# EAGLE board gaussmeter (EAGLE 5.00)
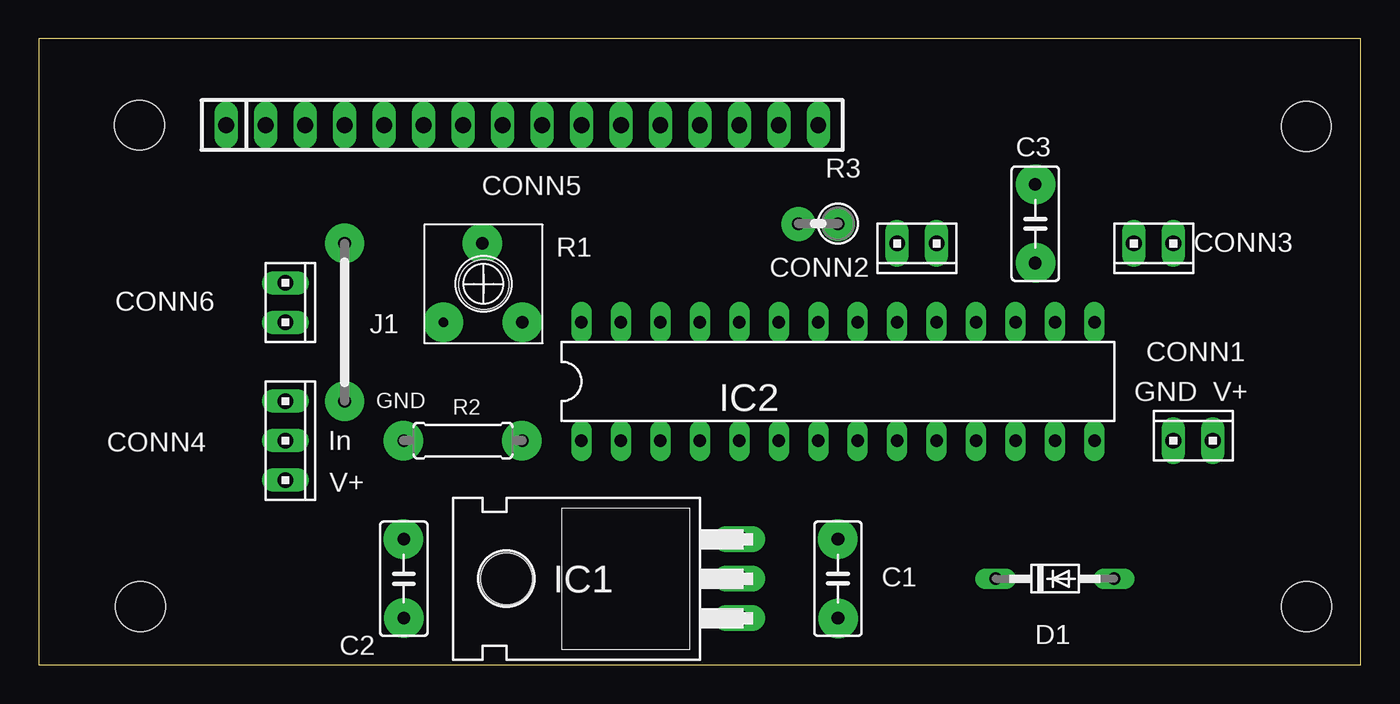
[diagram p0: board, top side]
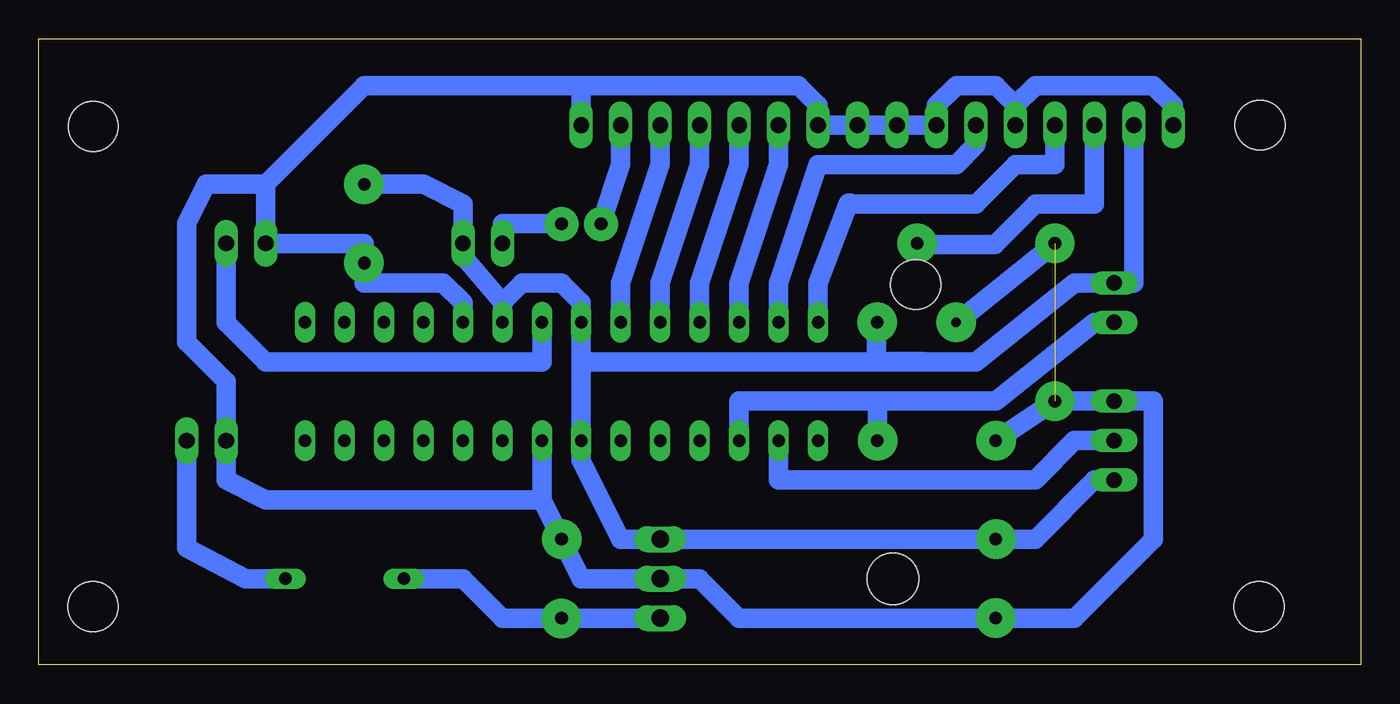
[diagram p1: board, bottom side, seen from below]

Size 85.07 x 40.31 mm. Coordinates in mm from the lower left corner, seen from the top.
Outline: 0,0 85.07,0 85.07,40.31 0,40.31 0,0
Copper layers (1*16): Top 0.035mm / dielectric 1.5mm / Bottom 0.035mm
Design rules "default *": minimum track width 50mil, minimum drill 24mil, track to track 8mil, track to pad 8mil, pad to pad 8mil, via to via 8mil, smd to smd 8mil, copper to edge 40mil, drill to drill 8mil, minimum pad ring 10mil, minimum via ring 8mil, stop-mask expansion 4mil, vias tented up to drill 0mil, thermal gap 10mil
Holes 3.2 mm at 28.63,24.49 6.48,34.75 81.57,34.67 81.59,3.76 6.54,3.76

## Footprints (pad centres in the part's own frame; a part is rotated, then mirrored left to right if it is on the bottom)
C5B3 = drill 0.813 pad 1.6 octagon: 1 -2.54,0; 2 2.54,0
10X02MTA = drill 1.016 long: 1 1.27,0; 2 -1.27,0
10X03MTA = drill 1.016 long: 1 2.54,0; 2 0,0; 3 -2.54,0
SIP-100-16V = drill 1.016 long: 1 -19.05,0; 2 -16.51,0; 3 -13.97,0; 4 -11.43,0; 5 -8.89,0; 6 -6.35,0; 7 -3.81,0; 8 -1.27,0; 9 1.27,0; 10 3.81,0; 11 6.35,0; 12 8.89,0; 13 11.43,0; 14 13.97,0; 15 16.51,0; 16 19.05,0
DO34-7 = drill 0.813 long: A 3.81,0; C -3.81,0
TO220H = drill 1.118 long: 1 -2.54,-10.16; 2 0,-10.16; 3 2.54,-10.16 | hole 3.302: 0,4.826
DIL28-3 = drill 0.813 long: 1 -16.51,-3.81; 2 -13.97,-3.81; 3 -11.43,-3.81; 4 -8.89,-3.81; 5 -6.35,-3.81; 6 -3.81,-3.81; 7 -1.27,-3.81; 8 1.27,-3.81; 9 3.81,-3.81; 10 6.35,-3.81; 11 8.89,-3.81; 12 11.43,-3.81; 13 13.97,-3.81; 14 16.51,-3.81; 15 16.51,3.81; 16 13.97,3.81; 17 11.43,3.81; 18 8.89,3.81; 19 6.35,3.81; 20 3.81,3.81; 21 1.27,3.81; 22 -1.27,3.81; 23 -3.81,3.81; 24 -6.35,3.81; 25 -8.89,3.81; 26 -11.43,3.81; 27 -13.97,3.81; 28 -16.51,3.81
10 = drill 0.813 pad 1.6 octagon: 1 -5.08,0; 2 5.08,0
TRIMMERORIZZ = drill 0.5 pad 1.016 round: P$1 -2.54,-2.54; P$2 2.54,-2.54; P$3 0,2.54
0207/7 = drill 0.813 octagon: 1 -3.81,0; 2 3.81,0
0207/2V = drill 0.813 octagon: 1 -1.27,0; 2 1.27,0

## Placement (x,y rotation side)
C1  330nF  [C5B3]  51.43,5.55 90 top
C2  100nF  [C5B3]  23.49,5.55 270 top
C3  100nF  [C5B3]  64.13,28.41 270 top
CONN1  +  [10X02MTA]  74.29,14.44 0 top
CONN2  [10X02MTA]  56.51,27.14 180 top
CONN3  [10X02MTA]  71.75,27.14 180 top
CONN4  [10X03MTA]  15.87,14.44 270 top
CONN5  [SIP-100-16V]  31.11,34.76 0 top
CONN6  [10X02MTA]  15.87,23.33 270 top
D1  1n4001  [DO34-7]  65.4,5.55 0 top
IC1  7805T  [TO220H]  34.92,5.55 90 top
IC2  PIC16F883  [DIL28-3]  51.43,18.25 0 top
J1  J10MM  [10]  19.68,22.06 90 top
R1  10k  [TRIMMERORIZZ]  28.62,24.54 0 top
R2  5k6  [0207/7]  27.3,14.44 0 top
R3  22  [0207/2V]  50.16,28.41 180 top

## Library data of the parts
C1-C3 = capacitor-wima
CONN1-CONN4 CONN6 = con-amp
CONN5 = con-hdrs40
D1 = diode
IC1 = linear
IC2 = microchip
J1 = jumper
R1-R3 = rcl

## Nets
+5V: C2.1 C3.1 CONN2.2 CONN4.1 CONN5.2 CONN6.2 IC1.3 IC2.20 R1.P$2
GND: C1.2 C2.2 C3.2 CONN1.2 CONN3.1 CONN4.3 CONN5.1 CONN5.5 CONN5.7 CONN5.8 CONN5.9 CONN5.10 CONN5.16 IC1.2 IC2.8 IC2.19 R2.1
N$1: C1.1 D1.C IC1.1
N$2: CONN5.15 R3.2
N$3: CONN5.4 IC2.28
N$4: CONN5.6 IC2.27
N$5: CONN5.11 IC2.26
N$6: CONN5.12 IC2.25
N$7: CONN5.13 IC2.24
N$8: CONN5.14 IC2.23
N$10: CONN1.1 D1.A
N$11: CONN5.3 R1.P$3
N$12: CONN3.2 IC2.21
N$16: CONN4.2 IC2.2
N$27: J1.1 R1.P$1
N$28: CONN2.1 R3.1
N$38: CONN6.1 IC2.3 R2.2

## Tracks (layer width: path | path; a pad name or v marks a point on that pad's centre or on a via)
+5V
  Bottom 1.27: CONN4.1 17.14,11.9 20.95,8.09 C2.1 IC1.3 47.62,8.09 50.16,13.17 50.16,19.52 | 50.16,19.52 50.16,23.33 51.43,24.6 53.97,24.6 55.24,23.33 | 17.14,24.6 14.6,24.6 CONN5.2 | 24.76,19.52 50.16,19.52 | 24.76,19.52 18.41,24.6 17.14,24.6 | CONN6.2 17.14,24.6 | 55.24,23.33 IC2.20 | 55.24,23.33 57.8,26.36 CONN2.2 57.78,29.68 60.32,30.95 C3.1 | R1.P$2 31.16,19.57 24.76,19.52
GND
  Bottom 1.27: R2.1 19.68,16.98 CONN4.3 13.33,16.98 13.33,8.09 18.41,3.01 C2.2 40,3.01 42.54,5.55 IC1.2 50.16,5.55 C1.2 52.7,10.63 | 52.7,10.63 IC2.8 | 52.7,10.63 70.48,10.63 73.02,11.9 CONN1.2 73.02,18.25 75.56,20.79 75.56,28.41 74.29,30.95 70.48,30.95 | IC2.19 57.78,23.33 59.05,24.6 64.13,24.6 C3.2 64.13,27.14 CONN3.1 70.48,30.95 | 70.48,30.95 64.13,37.3 50.16,37.3 | 50.16,37.3 CONN5.16 | 50.16,37.3 36.19,37.3 34.92,36.03 CONN5.10 | CONN5.10 CONN5.9 CONN5.8 CONN5.7 | CONN5.10 CONN5.7 | CONN5.7 27.3,36.03 26.03,37.3 23.49,37.3 22.22,36.03 | 22.22,36.03 CONN5.5 | 22.22,36.03 20.95,37.3 13.33,37.3 12.06,36.03 CONN5.1
N$1
  Bottom 1.27: IC1.1 C1.1 55.24,3.01 57.78,5.55 D1.C
N$2
  Bottom 1.27: CONN5.15 47.62,32.22 R3.2
N$3
  Bottom 1.27: IC2.28 34.92,24.6 32.96,29.73 32.84,29.73 32.83,29.74 32.77,29.68 24.76,29.68 22.22,32.22 19.68,32.22 CONN5.4
N$4
  Bottom 1.27: IC2.27 37.46,24.6 34.92,32.22 26.03,32.22 24.76,33.49 CONN5.6
N$5
  Bottom 1.27: IC2.26 40,24.6 37.46,32.22 CONN5.11
N$6
  Bottom 1.27: IC2.25 42.54,24.6 40,32.22 CONN5.12
N$7
  Bottom 1.27: IC2.24 45.08,24.6 42.54,32.22 CONN5.13
N$8
  Bottom 1.27: IC2.23 47.62,23.33 47.62,24.6 45.08,32.22 CONN5.14
N$10
  Bottom 1.27: D1.A 71.75,5.55 75.56,7.53 CONN1.1
N$11
  Bottom 1.27: R1.P$3 23.55,27.08 20.95,29.68 17.14,29.68 CONN5.3
N$12
  Bottom 1.27: CONN3.2 73.02,22.06 70.48,19.52 67.94,19.52 55.24,19.52 52.7,19.52 IC2.21
N$16
  Bottom 1.27: IC2.2 37.46,11.9 32.38,11.9 20.95,11.9 18.41,14.44 CONN4.2
N$26  (via drill 0.6 pad 2.54)
  other vias: 26.03,22.06 19.68,27.14 19.68,16.98
N$27  (1 unrouted)
  Bottom 1.27: 19.68,27.14 R1.P$1
N$28
  Bottom 1.27: CONN2.1 55.24,28.41 R3.1
N$30  (via drill 0.6 pad 2.54)
  other vias: 23.46,8.1 31.08,14.45 23.46,14.45
N$31  (via drill 0.6 pad 2.54)
  other vias: 23.49,3.02
N$32  (via drill 0.6 pad 2.54)
  other vias: 51.43,3
N$33  (via drill 0.6 pad 2.54)
  other vias: 51.42,8.11
N$36  (via drill 0.6 pad 2.54)
  other vias: 64.15,25.88
N$37  (via drill 0.6 pad 2.18, 0.6 pad 2.54)
  other vias: 64.14,30.93 51.44,28.39 48.9,28.39
N$38
  Bottom 1.27: CONN6.1 17.14,22.06 23.49,16.98 31.11,16.98 | 31.11,16.98 40,16.98 IC2.3 | 31.11,16.98 R2.2
N$42  (via drill 0.8 pad 2.54)
  other vias: 31.11,22.06
N$43  (via drill 0.8 pad 2.54)
  other vias: 28.55,27.15

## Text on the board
tNames: GND | GND | V+ | In | V+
